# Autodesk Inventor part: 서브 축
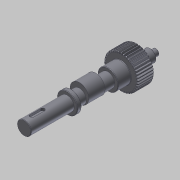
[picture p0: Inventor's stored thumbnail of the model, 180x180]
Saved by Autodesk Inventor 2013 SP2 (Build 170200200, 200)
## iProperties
Created: 2016-02
Part Number: 서브 축
Material: 강철, 연강
Document SubType Name: Modeling
Designer: mdu
Categories: <?xml version="1.0" encoding="UTF-16"?> <MemberInstance><Categories><FamilyTemplate><FamilyTemplateParameter ValueType="xs:double" Id="1" ObjectReferenceKey="da
Density: 7.86 g/cm^3
Mass: 506.173 g
Surface Area: 164.116 cm^2
Volume: 64.3986 cm^3
CustomPartVersion: 1
Author: mdu
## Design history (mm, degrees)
sketch "Sketch1"
  geometry: C1 r 21 at (0, 0)
  constraints: 1 centre point
  dimensions: "d0" = 42 diameter of C1 (= da_da)
extrude "Extrusion1" new body sketch "Sketch1" distance "d1" = 20 (= da_b); taper "d2" = 0 deg
workplane "Work Plane2"
feature "피치 지름" dims "d4" = 10, "d5" = 0
workplane "Work Plane8"
workplane "Work Plane9"
chamfer "모따기1" distance "d49" = 1; stored, may be unused: second distance "d50" = 2, angle "d51" = 45 deg
sketch "스케치3"
  geometry: C1 r 12.5 at (0, 0); 1 further point
  constraints: 1 centre point, 1 coincident
  dimensions: "d52" = 25 diameter of C1
extrude "돌출2" join sketch "스케치3" distance "d53" = 16; taper "d54" = 0 deg
sketch "스케치4"
  geometry: C1 r 8.5 at (0, 0); 1 further point
  constraints: 1 centre point, 1 coincident
  dimensions: "d55" = 17 diameter of C1
extrude "돌출3" join sketch "스케치4" distance "d56" = 103; taper "d57" = 0 deg
sketch "스케치5"
  geometry: C1 r 7.5 at (0, 0); 1 further point
  constraints: 1 centre point, 1 coincident
  dimensions: "d62" = 15 diameter of C1
extrude "돌출4" join sketch "스케치5" distance "d63" = 16; taper "d64" = 0 deg
sketch "스케치6"
  geometry: C1 r 4 at (0, 0); 1 further point
  constraints: 1 centre point, 1 coincident
  dimensions: "d65" = 8 diameter of C1
extrude "돌출5" join sketch "스케치6" distance "d66" = 7; taper "d67" = 0 deg
chamfer "모따기2" distance "d58" = 0.5; stored, may be unused: second distance "d59" = 2, angle "d60" = 45 deg
fillet "모깎기1" dims "d61" = 0.5
feature "스퍼 기어" dims "da_b" = 20, "da_d" = 40, "da_aw" = 31, "da_da" = 42, "da_df" = 37.5, "da_dw" = 40, angle "da_beta" = 0 deg, "da_lefttooth" = 0, "da_righttooth" = 0
node "작업 평면11"
sketch "스케치7"
  geometry: C1 r 8.5 at (0, 0) reference; C2 r 11.5 at (0, 3); 1 further point
  constraints: 1 centre point, 1 tangent, 1 vertical alignment
  dimensions: "d71" = 3 distance of C2.centre point (0, 0); "d72" = 23 diameter of C2 (derived)
extrude "돌출6" join sketch "스케치7" stored distance "d73" = 20; taper "d74" = 0 deg
node "작업 평면12"
sketch "스케치8"
  geometry: C1 r 12.5 at (0, 0) reference; 1 further point
extrude "돌출7" join sketch "스케치8" distance "d76" = 5; taper "d77" = 0 deg
chamfer "모따기3" distance "d78" = 0.5; stored, may be unused: second distance "d79" = 2, angle "d80" = 45 deg
sketch "스케치9"
  geometry: L1 (-8.5, 86)-(-8.5, 138.5) reference; L2 (-8, 139)-(8, 139) reference; L3 (0, 0)-(0, 139); L4 (-8.5, 115)-(0, 115); L5 (-8.5, 115)-(-8.5, 113.5); L6 (-7, 115)-(-8.5, 113.5)
  constraints: 8 end point, 4 point on line, 1 midpoint, 1 perpendicular
  dimensions: "d81" = 24 distance between parallel lines of L2 L4; "d82" = 45 deg angle of L6 L5; "d83" = 3 diameter of L5.end L4
revolve "회전1" sketch "스케치9" stored, may be unused: angle "d84" = 90 deg
sketch "스케치10"
  geometry: L1 (-8.5, 113.5)-(-7, 115) reference; L2 (-8.5, 116.5)-(-7, 115) reference; 2 further points
  constraints: 1 coincident
node "작업점1"
node "작업 평면14"
sketch "스케치11"
  geometry: L1 (8.5, 102.5)-(-8.5, 102.5) reference; L2 (0, 102.5)-(0, -36); L3 (-2.5, 93.5)-(-2.5, 80.5); L4 (2.5, 80.5)-(2.5, 93.5); L5 (-8, 103)-(8, 103) reference; A1 r 2.5 centre (0, 93.5) between (2.5, 93.5) and (-2.5, 93.5); A2 r 2.5 centre (0, 80.5) between (-2.5, 80.5) and (2.5, 80.5)
  constraints: 6 end point, 4 point on circle, 4 tangent, 2 centre point, 1 midpoint, 1 parallel, 1 perpendicular, 1 point on line, 1 vertical alignment
  dimensions: "d85" = 7 distance edge to line of A1 L5; "d86" = 18 dimension on A2 A1; "d87" = 5 distance between parallel lines of L3 L4
extrude "돌출8" cut sketch "스케치11" distance "d88" = 3; taper "d89" = 0 deg
body "Solid1"
sketch "Sketch2"
  geometry: C1 r 21 at (0, 0) reference; C2 r 20 at (0, 0)
  constraints: 1 centre point, 1 coincident
  dimensions: "d3" = 40 diameter of C2 (= da_dw)
body "Srf1"
other parameters: "d16" = 31 (= da_aw), "d17" = 0, "d34" = 4.5 deg (computed from da_z), "d39" = 0, "d41" = 0, "d43" = 31 (= da_aw), "d46" = 31 (= da_aw), "d47" = 0, "d48" = 0, "d68" = 25
